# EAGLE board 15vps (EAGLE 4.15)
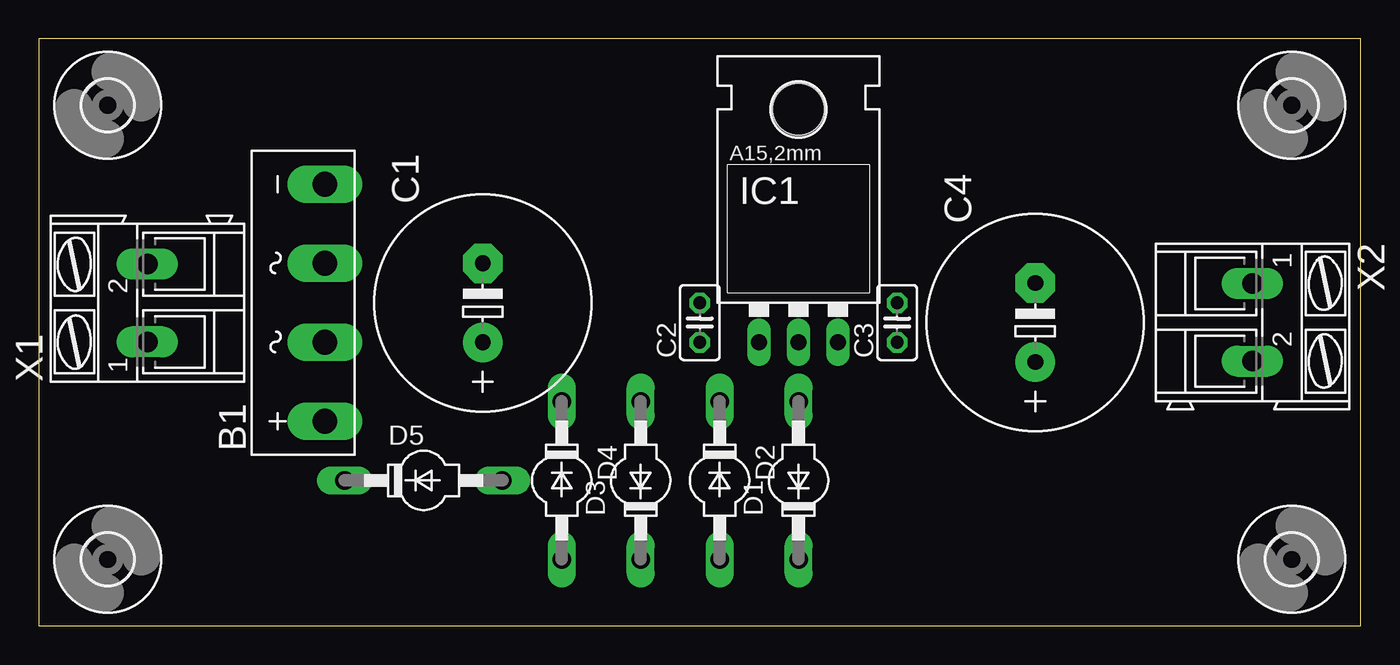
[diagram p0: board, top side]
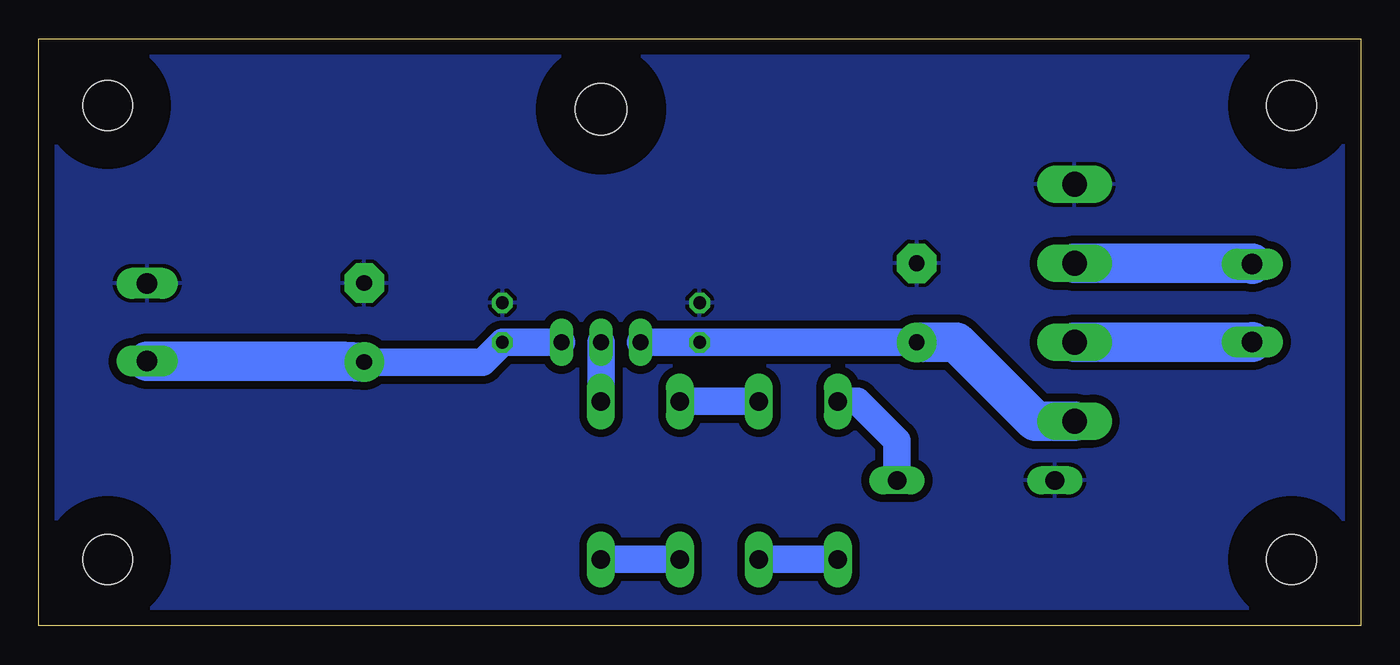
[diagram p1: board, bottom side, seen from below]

Size 85.07 x 37.77 mm. Coordinates in mm from the lower left corner, seen from the top.
Outline: 0,0 85.07,0 85.07,37.77 0,37.77 0,0
Copper layers (1*16): Top 0.035mm / dielectric 1.5mm / Bottom 0.035mm
Design rules "default": minimum track width 10mil, minimum drill 24mil, track to track 20mil, track to pad 20mil, pad to pad 20mil, via to via 20mil, smd to smd 8mil, copper to edge 40mil, drill to drill 8mil, minimum pad ring 10mil, minimum via ring 8mil, stop-mask expansion 4mil, vias tented up to drill 0mil, thermal gap 10mil

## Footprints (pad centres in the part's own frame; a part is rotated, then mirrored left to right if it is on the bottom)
KBL = drill 1.6 long: + -7.62,-1.27; - 7.62,-1.27; AC1 2.54,-1.27; AC2 -2.54,-1.27
E5-13 = drill 1.016 pad 2.54 round: + -2.54,0 | drill 1.016 pad 2.54 octagon: - 2.54,0
C025-025X050 = drill 0.813 octagon: 1 -1.27,0; 2 1.27,0
SOD57-10 = drill 1.194 long: A 5.08,0; C -5.08,0
3,2 = hole 3.2: 0,0
78XXL = drill 1.016 long: GND 0,-3.81; IN -2.54,-3.81; OUT 2.54,-3.81 | hole 3.302: 0,11.176
AK300/2 = drill 1.321 long: 1 -2.515,0; 2 2.489,0

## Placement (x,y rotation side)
B1  [KBL]  17.14,20.79 90 top
C1  [E5-13]  28.57,20.79 90 top
C2  [C025-025X050]  42.54,19.52 90 top
C3  [C025-025X050]  55.24,19.52 90 top
C4  [E5-13]  64.13,19.52 90 top
D1  BYV27  [SOD57-10]  48.89,9.36 90 top
D2  BYV27  [SOD57-10]  43.81,9.36 270 top
D3  BYV27  [SOD57-10]  38.73,9.36 90 top
D4  BYV27  [SOD57-10]  33.65,9.36 270 top
D5  BYV27  [SOD57-10]  24.76,9.36 0 top
H1  MOUNT-HOLE3.2  [3,2]  4.44,33.49 0 top
H2  MOUNT-HOLE3.2  [3,2]  4.44,4.28 0 top
H3  MOUNT-HOLE3.2  [3,2]  80.64,4.28 0 top
H4  MOUNT-HOLE3.2  [3,2]  80.64,33.49 0 top
IC1  [78XXL]  48.89,22.06 0 top
X1  [AK300/2]  6.98,20.79 90 top
X2  [AK300/2]  78.1,19.52 270 top

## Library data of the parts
B1 = rectifier
C1-C4 = rcl
D1-D5 = diode
H1-H4 = holes
IC1 = v-reg
X1 X2 = con-ptr500

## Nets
GND: B1.- C1.- C2.2 C3.2 C4.- D5.C X2.1
N$1: B1.AC2 X1.1
N$2: B1.AC1 X1.2
N$3: D4.C D5.A
N$5: B1.+ C1.+ C2.1 IC1.IN
N$6: D1.A IC1.GND
N$7: D1.C D2.A
N$8: D2.C D3.A
N$9: D3.C D4.A
N$10: C3.1 C4.+ IC1.OUT X2.2

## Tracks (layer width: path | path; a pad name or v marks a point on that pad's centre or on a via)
GND
  pour Bottom: -0.64,38.57 85.72,38.57 85.72,-0.8 -0.64,-0.8
N$1
  Bottom 2.54: X1.1 6.98,18.25 B1.AC2
N$2
  Bottom 2.54: X1.2 6.98,23.33 B1.AC1
N$3
  Bottom 1.778: D4.C 32.38,14.44 29.84,11.9 D5.A
N$5
  Bottom 1.778: C1.+ C2.1 IC1.IN
  Bottom 2.54: B1.+ 20.95,13.17 26.03,18.25 C1.+
N$6
  Bottom 1.778: D1.A IC1.GND
N$7
  Bottom 1.778: D2.A D1.C
N$8
  Bottom 1.778: D3.A D2.C
N$9
  Bottom 1.778: D4.A D3.C
N$10
  Bottom 1.778: C4.+ 56.51,16.98 C3.1 IC1.OUT
  Bottom 2.54: X2.2 65.45,17.03 C4.+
